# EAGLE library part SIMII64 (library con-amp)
AMP connector
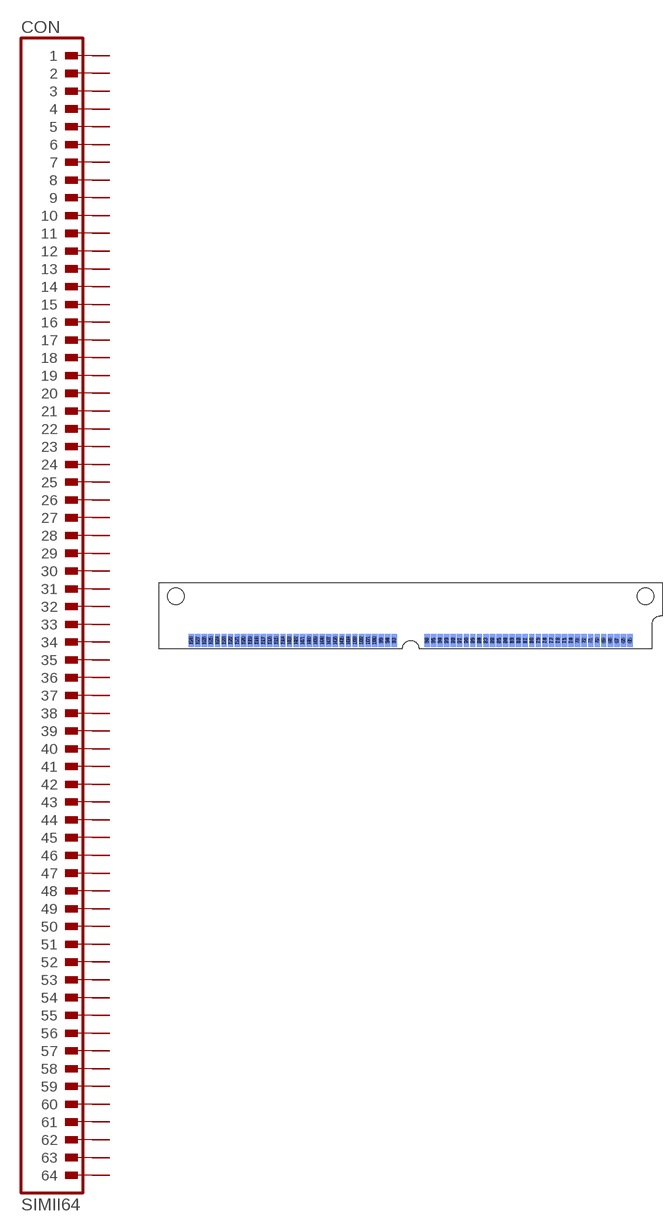
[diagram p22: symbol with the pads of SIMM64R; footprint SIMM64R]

Designator prefix CON

## SIMII64 (OC_FARNELL: unknown; OC_NEWARK: unknown)  [SIMM64R]
1  1  pas
2  2  pas
3  3  pas
4  4  pas
5  5  pas
6  6  pas
7  7  pas
8  8  pas
9  9  pas
10  10  pas
11  11  pas
12  12  pas
13  13  pas
14  14  pas
15  15  pas
16  16  pas
17  17  pas
18  18  pas
19  19  pas
20  20  pas
21  21  pas
22  22  pas
23  23  pas
24  24  pas
25  25  pas
26  26  pas
27  27  pas
28  28  pas
29  29  pas
30  30  pas
31  31  pas
32  32  pas
33  33  pas
34  34  pas
35  35  pas
36  36  pas
37  37  pas
38  38  pas
39  39  pas
40  40  pas
41  41  pas
42  42  pas
43  43  pas
44  44  pas
45  45  pas
46  46  pas
47  47  pas
48  48  pas
49  49  pas
50  50  pas
51  51  pas
52  52  pas
53  53  pas
54  54  pas
55  55  pas
56  56  pas
57  57  pas
58  58  pas
59  59  pas
60  60  pas
61  61  pas
62  62  pas
63  63  pas
64  64  pas
65  65  pas
66  66  pas
67  67  pas
68  68  pas
69  69  pas
70  70  pas
71  71  pas
72  72  pas
73  73  pas
74  74  pas
75  75  pas
76  76  pas
77  77  pas
78  78  pas
79  79  pas
80  80  pas
81  81  pas
82  82  pas
83  83  pas
84  84  pas
85  85  pas
86  86  pas
87  87  pas
88  88  pas
89  89  pas
90  90  pas
91  91  pas
92  92  pas
93  93  pas
94  94  pas
95  95  pas
96  96  pas
97  97  pas
98  98  pas
99  99  pas
100  100  pas
101  101  pas
102  102  pas
103  103  pas
104  104  pas
105  105  pas
106  106  pas
107  107  pas
108  108  pas
109  109  pas
110  110  pas
111  111  pas
112  112  pas
113  113  pas
114  114  pas
115  115  pas
116  116  pas
117  117  pas
118  118  pas
119  119  pas
120  120  pas
121  121  pas
122  122  pas
123  123  pas
124  124  pas
125  125  pas
126  126  pas
127  127  pas
128  128  pas

## Footprint SIMM64R (pad centres in mm)
SIMM II 64 Left Polarization
smd 1.041 x 2.54: 1 42.545,-8.636; 2 41.275,-8.636; 3 40.005,-8.636; 4 38.735,-8.636; 5 37.465,-8.636; 6 36.195,-8.636; 7 34.925,-8.636; 8 33.655,-8.636; 9 32.385,-8.636; 10 31.115,-8.636; 11 29.845,-8.636; 12 28.575,-8.636; 13 27.305,-8.636; 14 26.035,-8.636; 15 24.765,-8.636; 16 23.495,-8.636; 17 22.225,-8.636; 18 20.955,-8.636; 19 19.685,-8.636; 20 18.415,-8.636; 21 17.145,-8.636; 22 15.875,-8.636; 23 14.605,-8.636; 24 13.335,-8.636; 25 12.065,-8.636; 26 10.795,-8.636; 27 9.525,-8.636; 28 8.255,-8.636; 29 6.985,-8.636; 30 5.715,-8.636; 31 4.445,-8.636; 32 3.175,-8.636; 33 -3.175,-8.636; 34 -4.445,-8.636; 35 -5.715,-8.636; 36 -6.985,-8.636; 37 -8.255,-8.636; 38 -9.525,-8.636; 39 -10.795,-8.636; 40 -12.065,-8.636; 41 -13.335,-8.636; 42 -14.605,-8.636; 43 -15.875,-8.636; 44 -17.145,-8.636; 45 -18.415,-8.636; 46 -19.685,-8.636; 47 -20.955,-8.636; 48 -22.225,-8.636; 49 -23.495,-8.636; 50 -24.765,-8.636; 51 -26.035,-8.636; 52 -27.305,-8.636; 53 -28.575,-8.636; 54 -29.845,-8.636; 55 -31.115,-8.636; 56 -32.385,-8.636; 57 -33.655,-8.636; 58 -34.925,-8.636; 59 -36.195,-8.636; 60 -37.465,-8.636; 61 -38.735,-8.636; 62 -40.005,-8.636; 63 -41.275,-8.636; 64 -42.545,-8.636
smd 1.041 x 2.54 bottom: 65 42.545,-8.636; 66 41.275,-8.636; 67 40.005,-8.636; 68 38.735,-8.636; 69 37.465,-8.636; 70 36.195,-8.636; 71 34.925,-8.636; 72 33.655,-8.636; 73 32.385,-8.636; 74 31.115,-8.636; 75 29.845,-8.636; 76 28.575,-8.636; 77 27.305,-8.636; 78 26.035,-8.636; 79 24.765,-8.636; 80 23.495,-8.636; 81 22.225,-8.636; 82 20.955,-8.636; 83 19.685,-8.636; 84 18.415,-8.636; 85 17.145,-8.636; 86 15.875,-8.636; 87 14.605,-8.636; 88 13.335,-8.636; 89 12.065,-8.636; 90 10.795,-8.636; 91 9.525,-8.636; 92 8.255,-8.636; 93 6.985,-8.636; 94 5.715,-8.636; 95 4.445,-8.636; 96 3.175,-8.636; 97 -3.175,-8.636; 98 -4.445,-8.636; 99 -5.715,-8.636; 100 -6.985,-8.636; 101 -8.255,-8.636; 102 -9.525,-8.636; 103 -10.795,-8.636; 104 -12.065,-8.636; 105 -13.335,-8.636; 106 -14.605,-8.636; 107 -15.875,-8.636; 108 -17.145,-8.636; 109 -18.415,-8.636; 110 -19.685,-8.636; 111 -20.955,-8.636; 112 -22.225,-8.636; 113 -23.495,-8.636; 114 -24.765,-8.636; 115 -26.035,-8.636; 116 -27.305,-8.636; 117 -28.575,-8.636; 118 -29.845,-8.636; 119 -31.115,-8.636; 120 -32.385,-8.636; 121 -33.655,-8.636; 122 -34.925,-8.636; 123 -36.195,-8.636; 124 -37.465,-8.636; 125 -38.735,-8.636; 126 -40.005,-8.636; 127 -41.275,-8.636; 128 -42.545,-8.636
hole 3.175 at -45.517,0
hole 3.175 at 45.517,0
